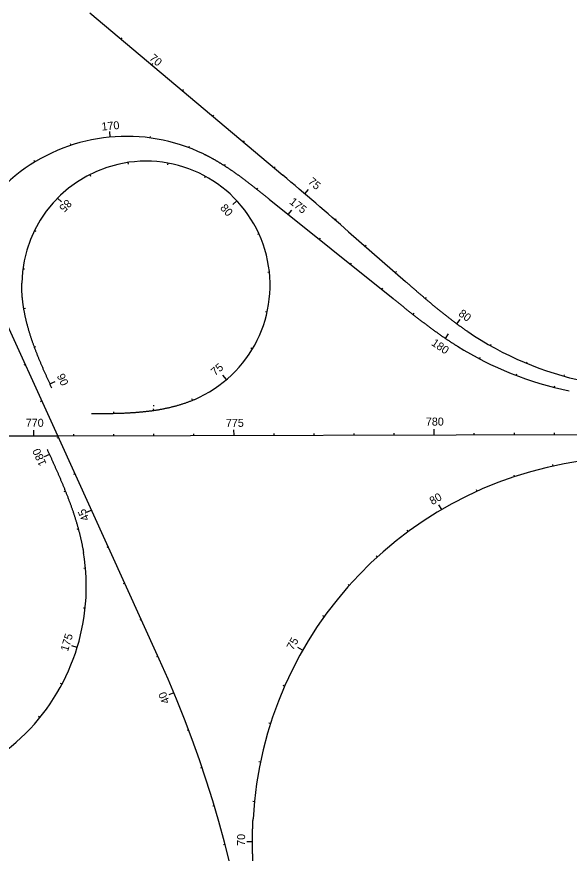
# Model space of a CAD drawing. Extents: x 448091 to 665917, y 1461380 to 1587607.
# Drawn here: x 557020 to 558400, y 1495926 to 1498016 of the extents above; entities that cross this region are included whole.
import ezdxf

# ---------------------------------------------------------------- set-up
doc = ezdxf.new("R2010")
doc.units = 0
doc.layers.add('TextShtNo', color=7, linetype='Continuous')
doc.layers.add('TextTitle', color=7, linetype='Continuous')

msp = doc.modelspace()

# ---------------------------------------------------------------- linework, layer by layer
at = {"layer": 'TextShtNo'}
for p, q in [((557202.7, 1498026.2), (557684.4, 1497620.5)), ((557122.6, 1496969.2), (556851.4, 1497565.8)), ((557650.9, 1497560.3), (557960, 1497312.1)), ((557849.1, 1497479), (557991, 1497354.9)), ((557122.6, 1496969.2), (558894, 1496974)), ((556841.6, 1496968.5), (557122.6, 1496969.2)), ((557376.3, 1496411), (557122.6, 1496969.2))]:
    msp.add_line(p, q, dxfattribs=at)
for centre, radius, start, end in [((557294.4, 1497276.6), 440.7, 64.1669, 189.9105), ((557342.9, 1497345.3), 310, 295.5683, 179.0306), ((550302.3, 1488856.1), 11459, 48.80752, 49.8929), ((558606.6, 1497906.5), 818.5, 235.8075, 258.2431), ((558567.4, 1497907.3), 842.5, 237.9675, 258.5422), ((558564, 1495960.8), 954.9, 95.4033, 176.9337), ((556673.1, 1496593), 520.9, 257.4087, 9.314), ((554768.3, 1495225.8), 2864.7, 349.9658, 24.4399)]:
    msp.add_arc(centre, radius, start, end, dxfattribs=at)
for points in [[(557650.9, 1497560.3), (557648.7, 1497562), (557646.6, 1497563.7), (557644.5, 1497565.4), (557642.4, 1497567.1), (557640.3, 1497568.7), (557638.2, 1497570.4), (557636.1, 1497572.1), (557634, 1497573.8), (557631.9, 1497575.5), (557629.8, 1497577.2), (557627.7, 1497578.9), (557625.5, 1497580.6), (557623.4, 1497582.2), (557621.3, 1497583.9), (557619.2, 1497585.6), (557617.1, 1497587.3), (557614.9, 1497588.9), (557612.8, 1497590.6), (557610.7, 1497592.3), (557608.6, 1497593.9), (557606.4, 1497595.6), (557604.3, 1497597.3), (557602.1, 1497598.9), (557600, 1497600.5), (557597.9, 1497602.2), (557595.7, 1497603.8), (557593.6, 1497605.5), (557591.4, 1497607.1), (557589.2, 1497608.7), (557587.1, 1497610.3), (557584.9, 1497611.9), (557582.7, 1497613.5), (557580.5, 1497615.1), (557578.4, 1497616.7), (557576.2, 1497618.3), (557574, 1497619.9), (557571.8, 1497621.5), (557569.6, 1497623.1), (557567.4, 1497624.6), (557565.2, 1497626.2), (557563, 1497627.7), (557560.7, 1497629.3), (557558.5, 1497630.8), (557556.3, 1497632.3), (557554, 1497633.8), (557551.8, 1497635.3), (557549.6, 1497636.8), (557547.3, 1497638.3), (557545, 1497639.8), (557542.8, 1497641.3), (557540.5, 1497642.8), (557538.2, 1497644.2), (557535.9, 1497645.7), (557533.6, 1497647.1), (557531.4, 1497648.5), (557529, 1497649.9), (557526.7, 1497651.3), (557524.4, 1497652.7), (557522.1, 1497654.1), (557519.8, 1497655.5), (557517.4, 1497656.8), (557515.1, 1497658.2), (557512.7, 1497659.5), (557510.4, 1497660.8), (557508, 1497662.1), (557505.6, 1497663.4), (557503.3, 1497664.7), (557500.9, 1497666), (557498.5, 1497667.2), (557496.1, 1497668.5), (557493.7, 1497669.7), (557491.3, 1497670.9), (557488.8, 1497672.1), (557486.4, 1497673.3)], [(557108, 1497088.5), (557106.4, 1497091.8), (557104.9, 1497095.2), (557103.4, 1497098.6), (557101.8, 1497102), (557100.3, 1497105.4), (557098.8, 1497108.8), (557097.3, 1497112.2), (557095.7, 1497115.6), (557094.2, 1497118.9), (557092.7, 1497122.3), (557091.2, 1497125.7), (557089.7, 1497129.1), (557088.2, 1497132.5), (557086.7, 1497135.9), (557085.2, 1497139.4), (557083.8, 1497142.8), (557082.3, 1497146.2), (557080.8, 1497149.6), (557079.4, 1497153), (557078, 1497156.5), (557076.5, 1497159.9), (557075.1, 1497163.3), (557073.7, 1497166.8), (557072.3, 1497170.2), (557071, 1497173.7), (557069.6, 1497177.1), (557068.3, 1497180.6), (557066.9, 1497184.1), (557065.6, 1497187.5), (557064.3, 1497191), (557063.1, 1497194.5), (557061.8, 1497198), (557060.6, 1497201.5), (557059.3, 1497205), (557058.1, 1497208.5), (557056.9, 1497212.1), (557055.8, 1497215.6), (557054.6, 1497219.1), (557053.5, 1497222.7), (557052.4, 1497226.2), (557051.3, 1497229.8), (557050.3, 1497233.3), (557049.3, 1497236.9), (557048.3, 1497240.5), (557047.3, 1497244.1), (557046.3, 1497247.7), (557045.4, 1497251.3), (557044.5, 1497254.9), (557043.6, 1497258.5), (557042.8, 1497262.1), (557042, 1497265.7), (557041.2, 1497269.4), (557040.5, 1497273), (557039.7, 1497276.7), (557039, 1497280.3), (557038.4, 1497284), (557037.8, 1497287.6), (557037.2, 1497291.3), (557036.6, 1497295), (557036.1, 1497298.6), (557035.6, 1497302.3), (557035.2, 1497306), (557034.8, 1497309.7), (557034.4, 1497313.4), (557034.1, 1497317.1), (557033.8, 1497320.8), (557033.5, 1497324.5), (557033.3, 1497328.2), (557033.1, 1497331.9), (557033, 1497335.7), (557032.9, 1497339.4), (557032.9, 1497343.1), (557032.9, 1497346.8), (557032.9, 1497350.5)], [(557991, 1497354.9), (557993, 1497353.1), (557995.1, 1497351.3), (557997.1, 1497349.6), (557999.1, 1497347.8), (558001.2, 1497346), (558003.2, 1497344.2), (558005.2, 1497342.4), (558007.3, 1497340.7), (558009.3, 1497338.9), (558011.3, 1497337.1), (558013.4, 1497335.3), (558015.4, 1497333.6), (558017.5, 1497331.8), (558019.5, 1497330), (558021.5, 1497328.2), (558023.6, 1497326.5), (558025.6, 1497324.7), (558027.7, 1497322.9), (558029.7, 1497321.2), (558031.8, 1497319.4), (558033.8, 1497317.7), (558035.9, 1497315.9), (558037.9, 1497314.1), (558040, 1497312.4), (558042, 1497310.6), (558044.1, 1497308.9), (558046.2, 1497307.1), (558048.2, 1497305.4), (558050.3, 1497303.6), (558052.4, 1497301.9), (558054.4, 1497300.2), (558056.5, 1497298.4), (558058.6, 1497296.7), (558060.7, 1497295), (558062.7, 1497293.2), (558064.8, 1497291.5), (558066.9, 1497289.8), (558069, 1497288.1), (558071.1, 1497286.4), (558073.2, 1497284.7), (558075.3, 1497283), (558077.4, 1497281.3), (558079.5, 1497279.6), (558081.6, 1497277.9), (558083.7, 1497276.2), (558085.8, 1497274.5), (558087.9, 1497272.8), (558090, 1497271.2), (558092.2, 1497269.5), (558094.3, 1497267.8), (558096.4, 1497266.2), (558098.6, 1497264.5), (558100.7, 1497262.8), (558102.8, 1497261.2), (558105, 1497259.6), (558107.1, 1497257.9), (558109.3, 1497256.3), (558111.5, 1497254.7), (558113.6, 1497253), (558115.8, 1497251.4), (558118, 1497249.8), (558120.1, 1497248.2), (558122.3, 1497246.6), (558124.5, 1497245), (558126.7, 1497243.4), (558128.9, 1497241.9), (558131.1, 1497240.3), (558133.3, 1497238.7), (558135.5, 1497237.2), (558137.7, 1497235.6), (558139.9, 1497234.1), (558142.2, 1497232.5), (558144.4, 1497231), (558146.6, 1497229.5)], [(557960, 1497312.1), (557962.1, 1497310.4), (557964.2, 1497308.7), (557966.3, 1497307), (557968.4, 1497305.3), (557970.5, 1497303.6), (557972.6, 1497301.9), (557974.7, 1497300.2), (557976.8, 1497298.6), (557978.9, 1497296.9), (557981, 1497295.2), (557983.1, 1497293.5), (557985.2, 1497291.8), (557987.3, 1497290.1), (557989.5, 1497288.4), (557991.6, 1497286.7), (557993.7, 1497285), (557995.8, 1497283.4), (557997.9, 1497281.7), (558000, 1497280), (558002.2, 1497278.3), (558004.3, 1497276.7), (558006.4, 1497275), (558008.5, 1497273.3), (558010.6, 1497271.6), (558012.8, 1497270), (558014.9, 1497268.3), (558017, 1497266.6), (558019.2, 1497265), (558021.3, 1497263.3), (558023.4, 1497261.7), (558025.6, 1497260), (558027.7, 1497258.4), (558029.9, 1497256.7), (558032, 1497255.1), (558034.2, 1497253.4), (558036.3, 1497251.8), (558038.5, 1497250.2), (558040.6, 1497248.5), (558042.8, 1497246.9), (558044.9, 1497245.3), (558047.1, 1497243.7), (558049.3, 1497242.1), (558051.4, 1497240.4), (558053.6, 1497238.8), (558055.8, 1497237.2), (558058, 1497235.6), (558060.2, 1497234), (558062.3, 1497232.5), (558064.5, 1497230.9), (558066.7, 1497229.3), (558068.9, 1497227.7), (558071.1, 1497226.1), (558073.3, 1497224.6), (558075.5, 1497223), (558077.7, 1497221.5), (558079.9, 1497219.9), (558082.2, 1497218.4), (558084.4, 1497216.8), (558086.6, 1497215.3), (558088.8, 1497213.8), (558091.1, 1497212.2), (558093.3, 1497210.7), (558095.6, 1497209.2), (558097.8, 1497207.7), (558100, 1497206.2), (558102.3, 1497204.7), (558104.6, 1497203.2), (558106.8, 1497201.8), (558109.1, 1497200.3), (558111.4, 1497198.8), (558113.6, 1497197.4), (558115.9, 1497195.9), (558118.2, 1497194.5), (558120.5, 1497193)], [(557207.1, 1497024.8), (557210.8, 1497024.8), (557214.6, 1497024.8), (557218.3, 1497024.9), (557222, 1497024.9), (557225.7, 1497024.9), (557229.4, 1497024.9), (557233.1, 1497024.9), (557236.9, 1497025), (557240.6, 1497025), (557244.3, 1497025), (557248, 1497025.1), (557251.7, 1497025.1), (557255.4, 1497025.2), (557259.1, 1497025.2), (557262.9, 1497025.3), (557266.6, 1497025.4), (557270.3, 1497025.5), (557274, 1497025.6), (557277.7, 1497025.7), (557281.4, 1497025.8), (557285.1, 1497026), (557288.9, 1497026.1), (557292.6, 1497026.3), (557296.3, 1497026.4), (557300, 1497026.6), (557303.7, 1497026.8), (557307.4, 1497027.1), (557311.1, 1497027.3), (557314.8, 1497027.6), (557318.5, 1497027.8), (557322.2, 1497028.1), (557325.9, 1497028.4), (557329.7, 1497028.8), (557333.4, 1497029.1), (557337, 1497029.5), (557340.7, 1497029.9), (557344.4, 1497030.3), (557348.1, 1497030.7), (557351.8, 1497031.2), (557355.5, 1497031.6), (557359.2, 1497032.1), (557362.9, 1497032.7), (557366.5, 1497033.2), (557370.2, 1497033.8), (557373.9, 1497034.4), (557377.5, 1497035), (557381.2, 1497035.7), (557384.8, 1497036.4), (557388.5, 1497037.1), (557392.1, 1497037.8), (557395.8, 1497038.6), (557399.4, 1497039.4), (557403, 1497040.2), (557406.6, 1497041.1), (557410.2, 1497042), (557413.8, 1497042.9), (557417.4, 1497043.9), (557421, 1497044.9), (557424.6, 1497045.9), (557428.1, 1497047), (557431.7, 1497048.1), (557435.2, 1497049.2), (557438.8, 1497050.4), (557442.3, 1497051.6), (557445.8, 1497052.8), (557449.3, 1497054.1), (557452.8, 1497055.4), (557456.2, 1497056.7), (557459.7, 1497058.1), (557463.1, 1497059.5), (557466.5, 1497061), (557469.9, 1497062.5), (557473.3, 1497064.1), (557476.7, 1497065.6)], [(557096, 1496935.8), (557097.5, 1496932.5), (557099.1, 1496929.1), (557100.6, 1496925.7), (557102.1, 1496922.3), (557103.7, 1496918.9), (557105.2, 1496915.5), (557106.7, 1496912.2), (557108.3, 1496908.8), (557109.8, 1496905.4), (557111.3, 1496902), (557112.8, 1496898.6), (557114.4, 1496895.2), (557115.9, 1496891.8), (557117.4, 1496888.4), (557118.9, 1496885), (557120.4, 1496881.6), (557121.9, 1496878.2), (557123.4, 1496874.8), (557124.8, 1496871.4), (557126.3, 1496868), (557127.8, 1496864.6), (557129.2, 1496861.2), (557130.7, 1496857.7), (557132.1, 1496854.3), (557133.6, 1496850.9), (557135, 1496847.5), (557136.4, 1496844), (557137.8, 1496840.6), (557139.2, 1496837.1), (557140.6, 1496833.7), (557142, 1496830.3), (557143.4, 1496826.8), (557144.8, 1496823.3), (557146.1, 1496819.9), (557147.5, 1496816.4), (557148.8, 1496812.9), (557150.1, 1496809.5), (557151.4, 1496806), (557152.7, 1496802.5), (557154, 1496799), (557155.2, 1496795.5), (557156.5, 1496792), (557157.7, 1496788.5), (557159, 1496785), (557160.2, 1496781.5), (557161.4, 1496778), (557162.5, 1496774.4), (557163.7, 1496770.9), (557164.8, 1496767.4), (557166, 1496763.8), (557167.1, 1496760.3), (557168.2, 1496756.7), (557169.2, 1496753.2), (557170.3, 1496749.6), (557171.3, 1496746.1), (557172.4, 1496742.5), (557173.4, 1496738.9), (557174.3, 1496735.3), (557175.3, 1496731.7), (557176.2, 1496728.1), (557177.2, 1496724.5), (557178.1, 1496720.9), (557178.9, 1496717.3), (557179.8, 1496713.7), (557180.6, 1496710.1), (557181.4, 1496706.5), (557182.2, 1496702.8), (557183, 1496699.2), (557183.7, 1496695.5), (557184.4, 1496691.9), (557185.1, 1496688.2), (557185.8, 1496684.6), (557186.4, 1496680.9), (557187.1, 1496677.3)], [(557639.4, 1495638.7), (557638.7, 1495643.7), (557638, 1495648.7), (557637.2, 1495653.7), (557636.5, 1495658.7), (557635.8, 1495663.7), (557635.1, 1495668.7), (557634.4, 1495673.8), (557633.7, 1495678.8), (557633, 1495683.8), (557632.3, 1495688.8), (557631.5, 1495693.8), (557630.9, 1495698.9), (557630.2, 1495703.9), (557629.5, 1495708.9), (557628.8, 1495713.9), (557628.1, 1495718.9), (557627.4, 1495724), (557626.8, 1495729), (557626.1, 1495734), (557625.5, 1495739), (557624.8, 1495744.1), (557624.2, 1495749.1), (557623.5, 1495754.1), (557622.9, 1495759.1), (557622.3, 1495764.2), (557621.7, 1495769.2), (557621.1, 1495774.2), (557620.5, 1495779.3), (557619.9, 1495784.3), (557619.4, 1495789.3), (557618.8, 1495794.4), (557618.3, 1495799.4), (557617.8, 1495804.5), (557617.2, 1495809.5), (557616.7, 1495814.5), (557616.2, 1495819.6), (557615.8, 1495824.6), (557615.3, 1495829.7), (557614.8, 1495834.7), (557614.4, 1495839.8), (557614, 1495844.8), (557613.6, 1495849.9), (557613.2, 1495854.9), (557612.8, 1495860), (557612.4, 1495865), (557612.1, 1495870.1), (557611.7, 1495875.1), (557611.4, 1495880.2), (557611.1, 1495885.3), (557610.9, 1495890.3), (557610.6, 1495895.4), (557610.4, 1495900.4), (557610.1, 1495905.5), (557609.9, 1495910.6), (557609.7, 1495915.6), (557609.6, 1495920.7), (557609.4, 1495925.8), (557609.3, 1495930.8), (557609.2, 1495935.9), (557609.1, 1495941), (557609.1, 1495946), (557609, 1495951.1), (557609, 1495956.2), (557609, 1495961.2), (557609.1, 1495966.3), (557609.1, 1495971.4), (557609.2, 1495976.4), (557609.3, 1495981.5), (557609.4, 1495986.6), (557609.6, 1495991.6), (557609.8, 1495996.7), (557610, 1496001.8), (557610.2, 1496006.8), (557610.5, 1496011.9)]]:
    msp.add_spline(points, degree=3, dxfattribs=at)
at = {"layer": 'TextTitle'}
for p, q in [((557280.7, 1497960.5), (557283.3, 1497963.6)), ((557357.2, 1497896.1), (557359.8, 1497899.1)), ((557433.7, 1497831.7), (557436.3, 1497834.7)), ((557510.2, 1497767.2), (557512.8, 1497770.3)), ((557253.8, 1497715.5), (557252.5, 1497729.4)), ((557353.5, 1497713.4), (557354.1, 1497717.3)), ((557586.7, 1497702.8), (557589.2, 1497705.9)), ((557156.1, 1497695.1), (557154.8, 1497698.9)), ((557450.3, 1497688.9), (557451.7, 1497692.6)), ((557065.5, 1497653.3), (557063.4, 1497656.7)), ((557297.6, 1497652), (557298.2, 1497648)), ((557397.2, 1497650.5), (557396.5, 1497646.5)), ((557539.2, 1497643.6), (557541.4, 1497646.9)), ((557663.2, 1497638.4), (557665.7, 1497641.4)), ((557202.7, 1497621.8), (557204.6, 1497618.2)), ((557491.1, 1497617.5), (557489.2, 1497614)), ((557620.1, 1497584.9), (557622.6, 1497588)), ((557739.5, 1497573.8), (557748.6, 1497584.4)), ((557122.3, 1497563.1), (557132.3, 1497553.3)), ((557569.8, 1497556.5), (557559.5, 1497546.9)), ((557698.1, 1497522.3), (557706.9, 1497533.2)), ((557815.3, 1497508.6), (557817.9, 1497511.6)), ((557064.6, 1497482), (557068.2, 1497480.2)), ((557625, 1497473.6), (557621.4, 1497472)), ((557776.1, 1497459.7), (557778.6, 1497462.8)), ((557890.6, 1497442.8), (557893.2, 1497445.8)), ((557854.1, 1497397.1), (557856.6, 1497400.2)), ((557035.6, 1497386.7), (557039.6, 1497386.2)), ((557651.2, 1497377.6), (557647.2, 1497377.1)), ((557965.8, 1497376.9), (557968.5, 1497379.9)), ((557932.1, 1497334.5), (557934.6, 1497337.6)), ((558041.3, 1497311.3), (558043.9, 1497314.3)), ((557037.8, 1497287.1), (557041.8, 1497287.8)), ((557645.5, 1497278.1), (557641.6, 1497279)), ((558010.2, 1497272), (558012.6, 1497275.2)), ((558119.3, 1497248.8), (558127.6, 1497260.1)), ((558090.6, 1497212.6), (558098.4, 1497224.2)), ((557064.4, 1497190.9), (557068.2, 1497192.3)), ((557608.6, 1497185.7), (557605.2, 1497187.7)), ((558203.2, 1497194.4), (558205.1, 1497197.8)), ((558176.2, 1497161.1), (558178, 1497164.6)), ((557041.7, 1497147.1), (557038.1, 1497145.5)), ((558293, 1497150.5), (558294.5, 1497154.2)), ((557544.3, 1497109.7), (557535.2, 1497120.3)), ((558267.3, 1497120), (558268.7, 1497123.7)), ((558387.4, 1497117.9), (558388.5, 1497121.8)), ((557103.3, 1497098.8), (557116.1, 1497104.6)), ((558362.6, 1497090), (558363.6, 1497093.9)), ((557083.1, 1497056.1), (557079.4, 1497054.4)), ((557459.2, 1497057.9), (557457.7, 1497061.6)), ((557363.2, 1497044.3), (557361.2, 1497044.3)), ((557362.7, 1497032.6), (557362.1, 1497036.6)), ((557263.1, 1497025.3), (557263, 1497029.3)), ((557062.9, 1496969.1), (557062.8, 1496983.1)), ((557162.9, 1496969.3), (557162.9, 1496973.3)), ((557262.9, 1496969.6), (557262.9, 1496973.6)), ((557362.9, 1496969.9), (557362.9, 1496973.9)), ((557462.9, 1496970.1), (557462.9, 1496974.1)), ((557562.9, 1496970.4), (557562.8, 1496984.4)), ((557662.9, 1496970.7), (557662.9, 1496974.7)), ((557762.9, 1496970.9), (557762.9, 1496974.9)), ((557862.9, 1496971.2), (557862.9, 1496975.2)), ((557962.9, 1496971.5), (557962.9, 1496975.5)), ((558062.9, 1496971.7), (558062.8, 1496985.7)), ((558162.9, 1496972), (558162.9, 1496976)), ((558262.9, 1496972.3), (558262.9, 1496976.3)), ((558362.9, 1496972.5), (558362.9, 1496976.5)), ((557124.5, 1496965), (557120.8, 1496963.4)), ((557101.9, 1496922.8), (557089.2, 1496917)), ((558359.8, 1496893.6), (558358.9, 1496897.5)), ((557165.8, 1496874), (557162.2, 1496872.4)), ((558263.4, 1496867.1), (558262.1, 1496870.9)), ((557141.7, 1496831), (557138, 1496829.5)), ((558170.3, 1496830.7), (558168.6, 1496834.4)), ((558081.5, 1496784.8), (558074.4, 1496796.9)), ((557207.2, 1496783), (557194.5, 1496777.2)), ((557174, 1496736.4), (557170.2, 1496735.4)), ((557998, 1496729.9), (557995.6, 1496733.1)), ((557248.6, 1496691.9), (557244.9, 1496690.3)), ((557920.7, 1496666.5), (557918, 1496669.5)), ((557192, 1496638.2), (557188, 1496637.9)), ((557290, 1496600.9), (557286.3, 1496599.2)), ((557850.5, 1496595.4), (557847.5, 1496598)), ((557191.1, 1496538.4), (557187.1, 1496538.8)), ((557788, 1496517.3), (557784.8, 1496519.7)), ((557331.3, 1496509.8), (557327.7, 1496508.2)), ((557171.1, 1496440.5), (557157.7, 1496444.6)), ((557734.1, 1496433.2), (557721.9, 1496440.1)), ((557372.7, 1496418.8), (557369.1, 1496417.2)), ((557132.9, 1496348.3), (557129.3, 1496350.2)), ((557689.3, 1496343.8), (557685.6, 1496345.4)), ((557412.7, 1496327.2), (557399.8, 1496321.8)), ((557077.7, 1496265), (557074.6, 1496267.6)), ((557654, 1496250.3), (557650.2, 1496251.5)), ((557449.6, 1496234.2), (557445.8, 1496232.8)), ((557483.1, 1496140), (557479.3, 1496138.7)), ((557628.8, 1496153.6), (557624.8, 1496154.4)), ((557613.7, 1496054.8), (557609.7, 1496055.2)), ((557513.4, 1496044.7), (557509.6, 1496043.6)), ((557540.3, 1495948.4), (557536.4, 1495947.4)), ((557609, 1495954.9), (557595, 1495954.9))]:
    msp.add_line(p, q, dxfattribs=at)

# ---------------------------------------------------------------- texts
for s, rotation, p in [('70', 319.8929, (557349.8, 1497910.1)), ('170', 5.283, (557233, 1497731.6)), ('75', 319.5321, (557746.2, 1497601.5)), ('85', 225.3531, (557145.5, 1497561.4)), ('175', 321.239, (557699.7, 1497550.7)), ('80', 312.9406, (557526.9, 1497537.2)), ('80', 323.6636, (558121.7, 1497270.7)), ('180', 325.7532, (558054, 1497196.9)), ('75', 40.528, (557515.6, 1497117.9)), ('90', 294.401, (557119.9, 1497119)), ('780', 0.1533, (558042, 1496994.6)), ('770', 0.1533, (557042.9, 1496991.6)), ('775', 0.1533, (557542.6, 1496991.4)), ('180', 114.3976, (557095.1, 1496899.3)), ('80', 30.3502, (558058.3, 1496795.7)), ('45', 114.439, (557202.3, 1496761.5)), ('175', 72.9823, (557148, 1496428.9)), ('75', 60.3514, (557710.2, 1496432.2)), ('40', 112.612, (557402.9, 1496304.1)), ('70', 90.0929, (557590.6, 1495944.7))]:
    msp.add_text(s, height=20, rotation=rotation, dxfattribs=at).set_placement(p)

doc.saveas('drawing.dxf')
